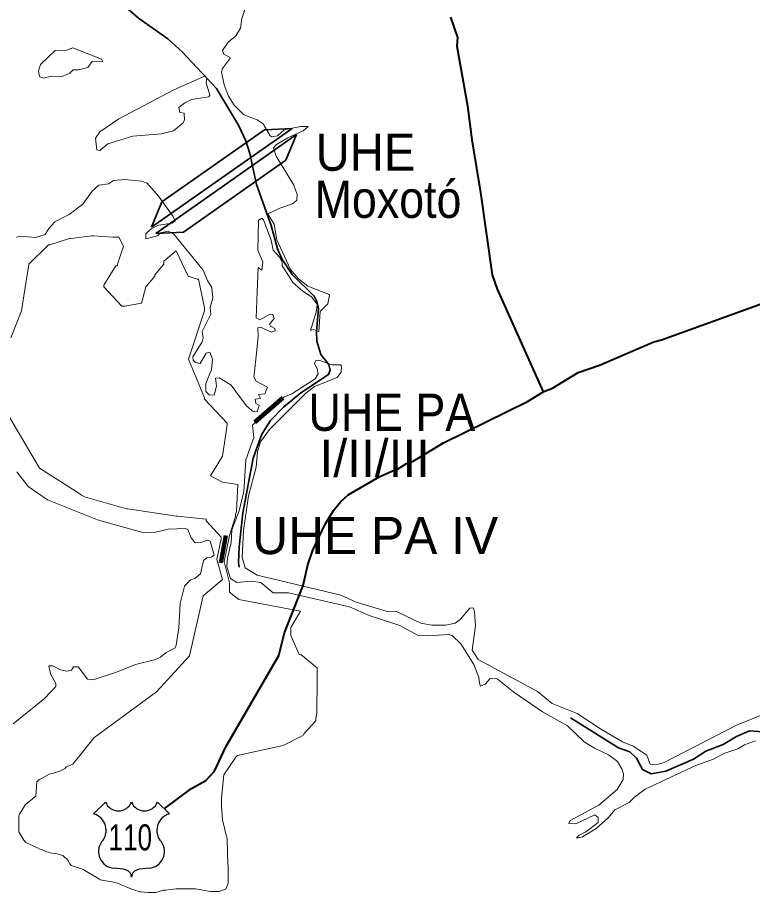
# Model space of a CAD drawing. Extents: x 553962 to 842807, y 8883888 to 9032388.
# Drawn here: x 580528 to 582504, y 8910928 to 8913281 of the extents above; entities that cross this region are included whole.
import ezdxf
from ezdxf.enums import TextEntityAlignment as Align

# ---------------------------------------------------------------- set-up
doc = ezdxf.new("R2010")
doc.units = 0
doc.header["$LTSCALE"] = 160
doc.linetypes.add('LONG_DASH_SHORT_DASH', pattern=[9.9, 6, -1.2, 1.5, -1.2])
doc.layers.add('6', color=7, linetype='Continuous', lineweight=13)

msp = doc.modelspace()

# ---------------------------------------------------------------- linework, layer by layer
at = {"layer": '6', "lineweight": 35}
for p, q in [((581266.4, 8912982.6), (580889, 8912717)), ((581278.8, 8912966.9), (580899.9, 8912700.2)), ((581192.1, 8912979.2), (580916.6, 8912785.3)), ((581192.1, 8912979.2), (581266.4, 8912982.6)), ((581249.7, 8912897.4), (581278.8, 8912966.9)), ((581249.7, 8912897.4), (580974.2, 8912703.5)), ((580916.6, 8912785.3), (580889, 8912717)), ((580899.9, 8912700.2), (580974.2, 8912703.5))]:
    msp.add_line(p, q, dxfattribs=at)
at = {"layer": '6', "lineweight": 90}
for p, q in [((581166.8, 8912193.2), (581242.1, 8912258.7)), ((581074.6, 8911814.7), (581088.7, 8911887.8))]:
    msp.add_line(p, q, dxfattribs=at)
at = {"layer": '6', "lineweight": 25}
for p, q in [((580732.9, 8911139.1), (580764.9, 8911171.1)), ((580904.8, 8911171.1), (580936.8, 8911139.1))]:
    msp.add_line(p, q, dxfattribs=at)
at = {"layer": '6', "linetype": 'LONG_DASH_SHORT_DASH', "lineweight": 35}
for points in [[(580811.7, 8913316.2), (580854, 8913279.9), (580932.2, 8913223.8), (580972.1, 8913187.7), (581063.2, 8913090.6), (581122.5, 8912991.5), (581142, 8912949.8), (581153.2, 8912915.6), (581171, 8912832.2), (581209.9, 8912721.7), (581227.6, 8912659.4), (581239.2, 8912631.8), (581266.5, 8912590.3), (581326.2, 8912531.5), (581332.6, 8912519.4), (581337.8, 8912498.5), (581331.8, 8912436.4), (581333.1, 8912411.1), (581343.9, 8912375), (581365.1, 8912348.2), (581368.5, 8912332.5), (581364.2, 8912321.3), (581289.9, 8912271.7), (581243.5, 8912233.1), (581208.6, 8912197.7), (581185.2, 8912160.5), (581161.6, 8912095.9), (581134.3, 8911949.1), (581124.7, 8911857.9), (581122.5, 8911815.6), (581124, 8911803.1)], [(582014.6, 8911397.4), (582144.1, 8911317), (582174.9, 8911306.2), (582192.1, 8911288.9), (582208.6, 8911258.7), (582231.6, 8911246.5), (582271.2, 8911254.3), (582345.6, 8911286.3), (582378.5, 8911308.3), (582425.2, 8911326.1), (582461.6, 8911347.7), (582496.6, 8911362.4), (582544.5, 8911359.4)]]:
    msp.add_lwpolyline(points, dxfattribs=at)
at = {"layer": '6'}
for points in [[(581309.8, 8912988.2), (581309.8, 8912988.2), (581289.7, 8912987.7), (581245.5, 8912978.7), (581227.2, 8912963.4), (581212, 8912960.1), (581207.2, 8912962.6), (581188.9, 8912994.9), (581172.8, 8913005.9), (581137.1, 8913019.9), (581110.7, 8913045.9), (581096, 8913070), (581084, 8913099.8), (581076.8, 8913135.4), (581079.3, 8913144), (581100.6, 8913172.4), (581083.2, 8913182.3), (581079.8, 8913192.1), (581095.1, 8913214.9), (581115, 8913232.4), (581127.7, 8913252.7), (581131.6, 8913278.4), (581140.4, 8913305.3)], [(581277.8, 8912788.2), (581279.5, 8912789.6), (581280, 8912805.1), (581271, 8912830.4), (581223.8, 8912908.6), (581216.6, 8912930.4), (581224.7, 8912939.7), (581254.8, 8912957.9), (581296.7, 8912976.6), (581308.1, 8912986.6), (581309.8, 8912988.2)], [(580525.8, 8912690.7), (580535.5, 8912693.2), (580577, 8912689.8), (580577, 8912689.8), (580602.6, 8912697.5), (580612.9, 8912714.1), (580629, 8912731.5), (580667.3, 8912751.5), (580704.2, 8912779), (580728.9, 8912814.4), (580747.1, 8912830.5), (580772.6, 8912833.5), (580786.6, 8912842.8), (580816.8, 8912845.3), (580861.8, 8912841.5), (580876.7, 8912835.6), (580907.3, 8912800.7), (580946.8, 8912745.9), (580951.8, 8912734.5), (580944.1, 8912728.4), (580907.7, 8912722.4), (580888.1, 8912713.2), (580873.7, 8912699.1), (580873.7, 8912686.1), (580905.1, 8912693.7), (580912.8, 8912702.2), (580933.6, 8912706.4), (580948.5, 8912698.3), (581027.9, 8912601.9), (581039, 8912573.9), (581050.5, 8912555), (581053.4, 8912527.1), (581046.2, 8912500.8), (581047.9, 8912483.1), (581025, 8912437.1), (581027.9, 8912419.8), (581024.9, 8912409), (580999.5, 8912368.6), (581000.8, 8912359.3), (581007.1, 8912353), (581019.3, 8912350.8), (581035.6, 8912378), (581045.2, 8912381), (581052.5, 8912362.4), (581049.6, 8912334.3), (581034.7, 8912296.8), (581034.8, 8912275.2), (581043.2, 8912266.3), (581057.1, 8912265), (581063.6, 8912289.2), (581060.7, 8912310.8), (581070.9, 8912312.5), (581081.6, 8912305.8)], [(581366.5, 8912535.8), (581309.1, 8912558.6), (581283.7, 8912578.6), (581262.3, 8912603.9), (581262.3, 8912603.9), (581225.9, 8912683.5), (581218.3, 8912725.1), (581201.7, 8912753.5), (581233.6, 8912768.4), (581267.9, 8912779.9), (581277.8, 8912788.2)], [(581172.7, 8912543.7), (581175, 8912608.9), (581185.1, 8912601.8), (581187.7, 8912624), (581174.9, 8912654.7), (581176.2, 8912736.1), (581185.3, 8912741.2), (581189.3, 8912737.1), (581210.6, 8912682.6), (581215.3, 8912655.5), (581233.2, 8912635.8), (581239.9, 8912622.3), (581240, 8912613.3), (581258.5, 8912584.3)], [(580510.6, 8912419.9), (580538.8, 8912492.6), (580559, 8912617.7), (580611.5, 8912670.2), (580615.5, 8912670.2), (580668, 8912686.4), (580672, 8912686.4), (580728.5, 8912694.4), (580732.5, 8912694.4), (580785, 8912690.4), (580793.1, 8912690.4), (580797.1, 8912690.4), (580801.1, 8912690.4), (580813.2, 8912666.2), (580797.1, 8912617.7), (580797.1, 8912613.7), (580793.1, 8912613.7), (580760.8, 8912561.2), (580760.8, 8912557.2), (580809.2, 8912504.7), (580813.2, 8912504.7), (580817.3, 8912504.7), (580861.7, 8912512.8), (580873.8, 8912557.2), (580898, 8912585.4), (580898, 8912589.5), (580922.2, 8912617.7), (580922.2, 8912621.8), (580922.2, 8912625.8), (580954.5, 8912654.1), (580986.8, 8912585.4), (581011, 8912577.4), (581015, 8912577.4), (581031.2, 8912500.7), (581031.2, 8912496.6), (581031.2, 8912492.6), (580988.2, 8912362.7), (581031.2, 8912258.5), (581031.2, 8912254.4), (581091.7, 8912189.8), (581091.7, 8912185.8), (581079.6, 8912101), (581047.3, 8912048.6)], [(581258.5, 8912584.3), (581268.3, 8912568.8), (581295.3, 8912545.3), (581319, 8912529.6), (581333.8, 8912510.2), (581332.8, 8912500.7)], [(581218.2, 8912471.5), (581214.4, 8912482.3), (581208, 8912482.9), (581179.6, 8912467.7), (581170.2, 8912473.2), (581172.7, 8912543.7)], [(581337.2, 8912437), (581338.1, 8912436.6), (581342.3, 8912490.1), (581362.3, 8912511), (581366.8, 8912535.7), (581366.5, 8912535.8)], [(581332.8, 8912500.7), (581331.5, 8912488.3), (581315.9, 8912439.5), (581316.2, 8912439.6), (581316.2, 8912440.5)], [(581169.9, 8912369.9), (581175.8, 8912423.6), (581174.5, 8912446.3), (581181.3, 8912448.5), (581211, 8912434.9), (581220.8, 8912438.5), (581220.4, 8912445.1), (581208.9, 8912451.1), (581205.5, 8912456.7), (581218.2, 8912471.5), (581218.2, 8912471.5)], [(581316.2, 8912439.6), (581324.1, 8912442.3), (581337.2, 8912437)], [(581135.5, 8911901.6), (581149.3, 8911994.6), (581170.2, 8912071.5), (581173.7, 8912113.4), (581181.2, 8912140.2), (581205.4, 8912173.1), (581304.6, 8912271.9), (581326.6, 8912288.6), (581388, 8912312.8), (581398.3, 8912327.2), (581399.7, 8912343.6), (581396.9, 8912346.6), (581374.1, 8912347), (581338.1, 8912359.7), (581329.6, 8912358.2), (581327, 8912349.8), (581333.7, 8912337.4), (581336.7, 8912322.7), (581329, 8912309.2), (581265.5, 8912268.8), (581244.2, 8912259.8), (581202.1, 8912226.9), (581160.5, 8912185.1), (581163.3, 8912151.7), (581142.6, 8912091.4), (581136.6, 8912006), (581124.1, 8911954.1), (581104.7, 8911903.6), (581102.9, 8911869.2), (581093, 8911827.2), (581091, 8911804.1), (581100.6, 8911772.3), (581118.2, 8911761.8), (581156.8, 8911764.7), (581182.7, 8911761.1), (581215.5, 8911733.5), (581257.2, 8911733.9), (581420.6, 8911696.1), (581473.7, 8911672.5), (581556.1, 8911645.9), (581603.5, 8911620.1), (581633.2, 8911618), (581687.3, 8911621.4), (581697.3, 8911618.8), (581720.2, 8911596.8), (581754.8, 8911541.3), (581768.5, 8911506.1), (581770.8, 8911491.1), (581773.4, 8911483.1), (581785.4, 8911488.5), (581798.7, 8911502.9), (581818.2, 8911502.4), (581863, 8911466.3), (581940, 8911413.8), (582006.9, 8911375.9), (582051.8, 8911333.2), (582079.1, 8911315.5), (582116.8, 8911298.3), (582141.3, 8911280.1), (582153.2, 8911260.5), (582157.4, 8911246.5), (582156.8, 8911231.9), (582140.6, 8911205), (582091.4, 8911162.7), (582014.5, 8911121.4)], [(581196.1, 8912276.3), (581200.4, 8912287), (581169.9, 8912302.8), (581163.9, 8912314.7), (581165.4, 8912328.8), (581169.9, 8912369.9)], [(581081.6, 8912305.8), (581103, 8912292.4), (581143.5, 8912237.3), (581160.1, 8912222.1), (581173.1, 8912220.7), (581178.4, 8912238.5), (581169, 8912243.4), (581167.3, 8912254.3), (581181.7, 8912256.8), (581176, 8912267.4), (581193.2, 8912269.3), (581196.1, 8912276.3)], [(580733.2, 8911343.8), (580902, 8911467.3), (580990.8, 8911564.2), (581027.1, 8911725.6), (581079.6, 8911770), (581064.5, 8911823.6), (581075.6, 8911879), (581075.6, 8911883.1), (581035.2, 8911927.5), (581035.2, 8911931.5), (580958.5, 8911939.6), (580954.5, 8911939.6), (580825.3, 8911959.8), (580821.3, 8911959.8), (580708.3, 8911992), (580700.2, 8911996.1), (580696.2, 8912000.1), (580587.3, 8912068.7), (580506.6, 8912206)], [(580896.6, 8911553.8), (580912.7, 8911561), (580928, 8911573.3), (580951, 8911585.2), (580955.3, 8911593.3), (580962.1, 8911639.2), (580965.5, 8911704.7), (580977.3, 8911751.3), (580993.9, 8911768.7), (581005.5, 8911772.6), (581020.3, 8911784.5), (581028.3, 8911821), (581038.6, 8911828.7), (581049.6, 8911829.9), (581056.8, 8911835.1), (581046.7, 8911872.7), (581039.4, 8911875.4), (581020.8, 8911869.1), (581005.8, 8911868.2), (580995.2, 8911881.4), (580986.3, 8911903.8), (580980.3, 8911907.2), (580933.2, 8911905.1), (580895.8, 8911896.2), (580867.6, 8911895.4), (580743.7, 8911929.8), (580608.6, 8911983.8), (580557.2, 8912019.4), (580527, 8912059)], [(581047.3, 8912048.6), (581079.2, 8912031.7), (581120.6, 8912025.3), (581117.4, 8911952), (581114.3, 8911945.6), (581114.3, 8911939.2), (581098.3, 8911888.2), (581083.9, 8911818.2), (581098.3, 8911761), (581098.3, 8911735.2), (581123.8, 8911716), (581289.6, 8911684.2)], [(582536.6, 8911407.9), (582459.2, 8911376.8), (582266.9, 8911277), (582247.9, 8911272), (582228.9, 8911273), (582219.8, 8911296.8), (582183.2, 8911321.6), (582155, 8911333.2), (582098.2, 8911365.9), (582032.6, 8911409.3), (581966.1, 8911435.9), (581926.1, 8911468.6), (581766.4, 8911554.5), (581751, 8911579.8), (581759.2, 8911645), (581757, 8911682.3), (581753.9, 8911693), (581744.2, 8911692.6), (581718.2, 8911662.4), (581704.6, 8911652.6), (581679.8, 8911647.1), (581642.2, 8911646.8), (581613.1, 8911652.5), (581547.6, 8911683.5), (581519.6, 8911684), (581438.5, 8911709), (581397.4, 8911727.8), (581173.1, 8911780.9), (581140.4, 8911800.9), (581132.1, 8911829.1), (581135.5, 8911901.6)], [(581091.6, 8911074.3), (581090.1, 8911078.7), (581079.7, 8911123.2), (581076.8, 8911160.2), (581076.8, 8911182.4), (581082.7, 8911244.6), (581115.3, 8911292), (581119.7, 8911296.5), (581196.7, 8911312.8), (581242.6, 8911323.1), (581291.5, 8911348.3), (581295.9, 8911349.8), (581298.9, 8911355.7), (581330, 8911389.8), (581330, 8911395.7), (581331.5, 8911400.1), (581332.9, 8911412), (581332.9, 8911423.8), (581334.4, 8911487.5), (581334.4, 8911492), (581334.4, 8911496.4), (581334.4, 8911532), (581330, 8911534.9), (581290, 8911567.5), (581285.5, 8911567.5), (581263.3, 8911619.3), (581263.3, 8911640.1), (581289.6, 8911684.2)], [(581289.6, 8911684.2), (581263.3, 8911640.1), (581263.3, 8911619.3), (581285.5, 8911567.5), (581290, 8911567.5), (581330, 8911534.9), (581334.4, 8911532), (581334.4, 8911496.4), (581334.4, 8911492), (581334.4, 8911487.5), (581332.9, 8911423.8), (581332.9, 8911412), (581331.5, 8911400.1), (581330, 8911395.7), (581330, 8911389.8), (581298.9, 8911355.7), (581295.9, 8911349.8), (581291.5, 8911348.3), (581242.6, 8911323.1), (581196.7, 8911312.8), (581119.7, 8911296.5), (581115.3, 8911292), (581082.7, 8911244.6), (581076.8, 8911182.4), (581076.8, 8911160.2), (581079.7, 8911123.2), (581090.1, 8911078.7), (581091.6, 8911074.3)], [(580516.9, 8911381.3), (580601.1, 8911449.4), (580631.4, 8911481.8), (580631.6, 8911490.3), (580617.5, 8911516), (580612.5, 8911537.2), (580623.1, 8911537.2), (580644.2, 8911526.6), (580661.3, 8911523.2), (580673.6, 8911525.3), (580678.7, 8911535.1), (580691.8, 8911535.1), (580716.5, 8911501.6), (580732.2, 8911499.4), (580794.7, 8911520.2), (580845.5, 8911541.4), (580896.6, 8911553.8)], [(580733.2, 8911343.8), (580706.6, 8911309.8), (580677, 8911272.8), (580671.1, 8911269.8), (580659.2, 8911265.3), (580656.3, 8911260.9), (580640, 8911253.5), (580635.5, 8911252), (580625.2, 8911249.1), (580613.3, 8911246.1), (580592.6, 8911234.2), (580586.7, 8911231.3), (580580.7, 8911225.4), (580577.8, 8911186.8), (580554.1, 8911167.6), (580549.7, 8911164.6), (580533.4, 8911138), (580531.9, 8911133.5), (580531.9, 8911123.2), (580531.9, 8911095), (580531.9, 8911090.6), (580545.2, 8911068.4), (580551.1, 8911062.4), (580582.2, 8911047.6), (580588.2, 8911044.7), (580592.6, 8911043.2), (580605.9, 8911037.2), (580611.8, 8911035.8), (580616.3, 8911034.3), (580635.5, 8911031.3), (580640, 8911029.8), (580650.3, 8911026.9), (580656.3, 8911021), (580660.7, 8911018), (580665.1, 8911012.1), (580668.1, 8911006.2), (580672.6, 8911000.2), (580700.7, 8910991.3), (580705.1, 8910989.9), (580746.6, 8910964.7), (580751, 8910961.7), (580786.6, 8910955.8), (580796.9, 8910952.8), (580835.4, 8910936.5), (580841.3, 8910935.1), (580856.2, 8910929.1), (580860.6, 8910929.1), (580878.4, 8910927.7), (580884.3, 8910927.7), (580894.7, 8910927.7), (580900.6, 8910927.7), (580921.3, 8910933.6), (580927.2, 8910933.6), (580955.3, 8910938), (580967.2, 8910938), (581007.2, 8910938), (581047.2, 8910930.6), (581069.4, 8910930.6), (581088.6, 8910936.5), (581094.5, 8910952.8), (581094.5, 8910957.3), (581094.5, 8910994.3), (581093.1, 8911026.9), (581093.1, 8911032.8), (581091.6, 8911074.3)], [(581091.6, 8911074.3), (581093.1, 8911032.8), (581093.1, 8911026.9), (581094.5, 8910994.3), (581094.5, 8910957.3), (581094.5, 8910952.8), (581088.6, 8910936.5), (581069.4, 8910930.6), (581047.2, 8910930.6), (581007.2, 8910938), (580967.2, 8910938), (580955.3, 8910938), (580927.2, 8910933.6), (580921.3, 8910933.6), (580900.6, 8910927.7), (580894.7, 8910927.7), (580884.3, 8910927.7), (580878.4, 8910927.7), (580860.6, 8910929.1), (580856.2, 8910929.1), (580841.3, 8910935.1), (580835.4, 8910936.5), (580796.9, 8910952.8), (580786.6, 8910955.8), (580751, 8910961.7), (580746.6, 8910964.7), (580705.1, 8910989.9), (580700.7, 8910991.3), (580672.6, 8911000.2), (580668.1, 8911006.2), (580665.1, 8911012.1), (580660.7, 8911018), (580656.3, 8911021), (580650.3, 8911026.9), (580640, 8911029.8), (580635.5, 8911031.3), (580616.3, 8911034.3), (580611.8, 8911035.8), (580605.9, 8911037.2), (580592.6, 8911043.2), (580588.2, 8911044.7), (580582.2, 8911047.6), (580551.1, 8911062.4), (580545.2, 8911068.4), (580531.9, 8911090.6), (580531.9, 8911095), (580531.9, 8911123.2), (580531.9, 8911133.5), (580533.4, 8911138), (580549.7, 8911164.6), (580554.1, 8911167.6), (580577.8, 8911186.8), (580580.7, 8911225.4), (580586.7, 8911231.3), (580592.6, 8911234.2), (580613.3, 8911246.1), (580625.2, 8911249.1), (580635.5, 8911252), (580640, 8911253.5), (580656.3, 8911260.9), (580659.2, 8911265.3), (580671.1, 8911269.8), (580677, 8911272.8), (580706.6, 8911309.8), (580733.2, 8911343.8)], [(582014.5, 8911121.4), (582010.5, 8911113), (582029.1, 8911112.6), (582080.3, 8911136.5), (582089.3, 8911129), (582089.3, 8911116.2), (582056.3, 8911091.3), (582038, 8911081.5), (582030.9, 8911073.5), (582047.2, 8911077.7), (582084.2, 8911100), (582117.1, 8911129.1), (582134.6, 8911150.4), (582172.3, 8911170.2), (582186.7, 8911184.5), (582215.5, 8911205.5), (582353.6, 8911270.2), (582399.6, 8911286.5), (582427.2, 8911301.9), (582464.8, 8911313.9), (582482.7, 8911325), (582512.2, 8911335.3)]]:
    msp.add_lwpolyline(points, dxfattribs=at)
at = {"layer": '6', "lineweight": 40}
for points in [[(581692.8, 8913282), (581711.4, 8913227.6), (581709.7, 8913204.2), (581738.2, 8913043.9), (581749.4, 8912952.6), (581773.3, 8912810.4), (581804.3, 8912589.4), (581818.2, 8912550.3), (581941.2, 8912274)], [(581088.7, 8911319.2), (581230.6, 8911565.6), (581246.6, 8911626.2), (581295.9, 8911753.5), (581309.3, 8911809.4), (581322.7, 8911848.3), (581355.5, 8911918.2), (581377.7, 8911955.6), (581396.6, 8911978.5), (581417.4, 8911997.1), (581502.6, 8912046.4), (581540.6, 8912063.6), (581547.6, 8912064.2), (581573.9, 8912081.4), (581591.7, 8912087.9), (581673.8, 8912137.2), (581899.5, 8912248.7), (581943.6, 8912275.5), (581967, 8912284.7), (582035.6, 8912326.1), (582092.7, 8912345.9), (582239.2, 8912409.1), (582260, 8912414.3), (582602, 8912537.9)], [(580922.7, 8911153.1), (580996.2, 8911207.1), (581034.8, 8911228.8), (581058, 8911254.4), (581088.7, 8911319.2)]]:
    msp.add_lwpolyline(points, dxfattribs=at)
at = {"layer": '6'}
for points in [[(580677.4, 8913199.3), (580754.6, 8913169.1), (580757.7, 8913161.8), (580729.4, 8913163.2), (580717.7, 8913147), (580692.7, 8913140.2), (580677.9, 8913140.2), (580669, 8913131.7), (580648.6, 8913122.4), (580619.7, 8913123.6), (580597.1, 8913117.7), (580587.8, 8913122.8), (580585.2, 8913136.5), (580590.4, 8913155), (580629.9, 8913192.5), (580660.4, 8913193.7)], [(580749.7, 8912974.1), (580801.2, 8913008.5), (580948.9, 8913087.1), (581033.9, 8913124), (581037.3, 8913116.8), (581035.2, 8913105.4), (581045.7, 8913072.2), (581042.7, 8913067.9), (580996, 8913061.1), (580977.8, 8913051.8), (580962.2, 8913039.1), (580964.6, 8913025.5), (580976, 8913023.8), (580976.9, 8913004.7), (580972.7, 8912997.5), (580948.1, 8912976.6), (580915.4, 8912968.6), (580838.8, 8912961.7), (580770.9, 8912941.3), (580750.1, 8912923.1), (580741.6, 8912925.3), (580737.8, 8912956.3)]]:
    msp.add_lwpolyline(points, close=True, dxfattribs=at)
at = {"layer": '6', "lineweight": 25}
for centre, radius, start, end in [((580799.9, 8911184.5), 37.4, 200.9593, 339.0407), ((580869.8, 8911184.5), 37.4, 200.9593, 339.0407), ((580720.5, 8911094.7), 46.1, 317.5721, 74.3689), ((580949.2, 8911094.7), 46.1, 105.6277, 222.4279), ((580791.2, 8911037.7), 44.9, 144.7373, 264.6578), ((580878.5, 8911037.7), 44.9, 275.3422, 35.2627), ((580786.8, 8910875), 118, 72.8937, 89.9006), ((580816, 8910969.7), 18.9, 357.6934, 72.9296), ((580853.7, 8910969.7), 18.9, 107.0704, 182.3065), ((580882.9, 8910875), 118, 90.0994, 107.1063)]:
    msp.add_arc(centre, radius, start, end, dxfattribs=at)

# ---------------------------------------------------------------- texts
at = {"layer": '6'}
for s, height, width, p in [('UHE', 100, 0.95, (581464.1, 8912869.1)), ('Moxotó', 100, 0.9, (581524.5, 8912742.3)), ('UHE PA', 100, 0.9, (581534.8, 8912169.4)), ('110', 70, 0.75, (580831.6, 8911041.1))]:
    msp.add_text(s, height=height, dxfattribs=dict(at, width=width)).set_placement(p, align=Align.CENTER)
for s, p in [('I/II/III', (581488.8, 8912045.7)), ('UHE PA IV', (581490, 8911837.9))]:
    msp.add_text(s, height=100, dxfattribs=at).set_placement(p, align=Align.CENTER)

doc.saveas('drawing.dxf')
